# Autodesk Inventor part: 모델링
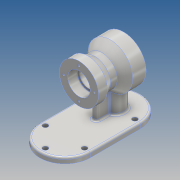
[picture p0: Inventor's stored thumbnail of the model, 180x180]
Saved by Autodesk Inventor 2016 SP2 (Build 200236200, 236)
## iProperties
Created: 2020-01
Part Number: 모델링
Material: 알루미늄 6061
Document SubType Name: Modeling
Designer: EZ
Density: 2.7 g/cm^3
Appearance: 알루미늄 - 평지
Author: EZ
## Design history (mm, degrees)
sketch "스케치1"
  geometry: L1 (-45, 0)-(-45, -90); L2 (45, 0)-(45, -90); L3 (0, 45)-(0, -135); A1 r 45 centre (0, 0) between (45, 0) and (-45, 0); A2 r 45 centre (0, -90) between (-45, -90) and (45, -90); 1 further point
  constraints: 6 end point, 6 point on circle, 2 centre point, 2 tangent, 1 coincident, 1 vertical
  dimensions: "d3" = 45 distance between parallel lines of L3 L1; "d4" = 180 distance of L3.end L3.start; "d6" = 90 distance between parallel lines of L2 L1
extrude "돌출1" new body sketch "스케치1" distance "d7" = 10; taper "d8" = 0 deg
fillet "모깎기1" dims "d9" = 3
sketch "스케치2"
  geometry: L1 (0, 0)-(-90, 0) reference; L2 (45, 0)-(45, 7) reference; L3 (15, 80)-(15, 120); L4 (15, 120)-(-9, 120); L5 (-9, 120)-(-23.897, 107.5); L6 (-23.897, 107.5)-(-36.01, 107.5); L7 (-36.01, 107.5)-(-49, 115); L8 (-49, 115)-(-65, 115); L9 (-65, 115)-(-65, 80); L10 (-65, 80)-(15, 80)
  constraints: 16 end point, 3 perpendicular, 2 parallel, 1 vertical
  dimensions: "d19" = 80 distance between parallel lines of L10 L1; "d20" = 80 distance between parallel lines of L9 L3; "d21" = 24 distance from line of L4.end L3; "d22" = 55 diameter of L6 L10; "d23" = 16 distance of L7.end L8.end; "d24" = 80 diameter of L4 L10; "d25" = 70 diameter of L8 L10; "d26" = 40 deg angle of L5 L6; "d27" = 30 deg angle of L7 L6; "d28" = 30 distance between parallel lines of L2 L3
revolve "회전1" sketch "스케치2" stored, may be unused: angle "d29" = 90 deg
sketch "스케치3"
  geometry: L1 (45, 0)-(45, -90) reference; L2 (-45, -90)-(-45, 0) reference; L3 (35, -90)-(35, 0); L4 (-35, 0)-(-35, -90); C1 r 4.5 at (35, 0); C2 r 4.5 at (35, -90); C3 r 4.5 at (0, -125); C4 r 4.5 at (-35, -90); C5 r 4.5 at (-35, 0); C6 r 4.5 at (0, 35); A1 r 45 centre (0, -90) between (-45, -90) and (45, -90) reference; A2 r 45 centre (0, 0) between (45, 0) and (-45, 0) reference; A3 r 35 centre (0, 0) between (35, 0) and (-35, 0); A4 r 35 centre (0, -90) between (-35, -90) and (35, -90); 4 further points
  constraints: 8 centre point, 8 point on circle, 5 coincident, 4 end point, 4 horizontal alignment, 2 point on line, 1 vertical alignment, 3 other
  dimensions: "d30" = 9 diameter of C1; "d31" = 9 diameter of C2; "d32" = 9 diameter of C3; "d33" = 9 diameter of C4; "d34" = 9 diameter of C5; "d35" = 9 diameter of C6; "d36" = 10 distance between parallel lines of L1 L3
extrude "돌출2" cut sketch "스케치3" distance "d37" = 10; taper "d38" = 0 deg
sketch "스케치4"
  geometry: L1 (45, -90)-(45, 0) reference; L2 (-45, 0)-(-45, -90) reference; L3 (0, 45)-(0, -135); L4 (5, -15.199)-(5, -34); L5 (-5, -15.199)-(-5, -34); A1 r 16 centre (0, 0) between (5, -15.199) and (-5, -15.199); A2 r 45 centre (0, 0) between (45, 0) and (-45, 0) reference; A3 r 45 centre (0, -90) between (-45, -90) and (45, -90) reference; A4 r 5 centre (0, -34) between (-5, -34) and (5, -34); 2 further points
  constraints: 7 point on circle, 6 end point, 2 centre point, 2 point on line, 2 tangent, 2 vertical, 1 coincident
  dimensions: "d39" = 32 diameter of A1; "d88" = 50 distance of point (0, 16) A4.centre; "d89" = 10 distance between parallel lines of L5 L4
extrude "돌출3" join sketch "스케치4" distance "d43" = 55; taper "d44" = 0 deg
sketch "스케치5"
  geometry: A1 r 40 centre (0, 0) between (-13.229, 37.749) and (13.229, 37.749) reference; 5 further points
  constraints: 1 vertical alignment, 5 other
  dimensions: "d45" = 33 distance of point (0, -33) A1.centre; "d48" = 360 deg dimension on A1.centre point (0, -33) (derived)
hole "구멍1" sketch "스케치5" at (0, -33), (33, 0), (0, 33), (-33, 0) diameter "d50" = 3.242; stored, may be unused: countersink angle "d54" = 90 deg, drill point angle "d56" = 118 deg; dims "d51" = 9, "d52" = 4, "d53" = 2, "d55" = 11
sketch "스케치6"
  geometry: C1 r 26 at (0, 0); A1 r 40 centre (0, 0) between (-13.229, 37.749) and (13.229, 37.749) reference; 1 further point
  constraints: 1 centre point, 1 coincident
  dimensions: "d57" = 52 diameter of C1
extrude "돌출4" cut sketch "스케치6" distance "d58" = 20; taper "d59" = 0 deg
fillet "모깎기2" dims "d60" = 0.3
chamfer "모따기1" distance "d61" = 1; stored, may be unused: second distance "d62" = 2, angle "d63" = 45 deg
sketch "스케치7"
  geometry: C1 r 35 at (0, 0) reference; 5 further points
  constraints: 1 vertical alignment, 5 other
  dimensions: "d64" = 27.5 distance of point (0, 27.5) C1.centre; "d67" = 360 deg dimension on C1.centre point (0, 27.5) (derived)
hole "구멍2" sketch "스케치7" at (0, 27.5), (-27.5, 0), (0, -27.5), (27.5, 0) diameter "d69" = 3.242; stored, may be unused: countersink angle "d73" = 90 deg, drill point angle "d75" = 118 deg; dims "d70" = 9, "d71" = 4, "d72" = 2, "d74" = 11
sketch "스케치8"
  geometry: C1 r 35 at (0, 0) reference; C2 r 20 at (0, 0); 1 further point
  constraints: 1 centre point, 1 coincident
  dimensions: "d76" = 40 diameter of C2
extrude "돌출5" cut sketch "스케치8" distance "d77" = 17; taper "d78" = 0 deg
sketch "스케치9"
  geometry: C1 r 35 at (0, 0) reference; C2 r 16 at (0, 0); A1 r 27.5 centre (0, 0) between (4.578, -27.116) and (-4.578, -27.116) reference; 1 further point
  constraints: 1 centre point, 1 coincident, 1 horizontal alignment
  dimensions: "d79" = 32 diameter of C2
extrude "돌출6" cut sketch "스케치9" stored distance "d80" = 17; taper "d81" = 0 deg
sketch "스케치10"
  geometry: L1 (6.573, 82.099)-(6.573, 45.203); L2 (6.573, 45.203)-(1.77, 45.203); L3 (1.77, 45.203)-(1.77, 82.099); L4 (1.77, 82.099)-(6.573, 82.099); L5 (0, 135)-(7, 135) reference; L6 (0, 90)-(0, 0) reference; 1 further point
  constraints: 2 other
  dimensions: "d82" = 70 distance from line of point (4, 65) L5; "d83" = 4 distance from line of point (4, 65) L6
feature "엠보싱1" sketch "스케치10" dims "d3" = 45, "d4" = 180, "d6" = 90, "d20" = 80, "d84" = 0.5, "d85" = 0
fillet "모깎기3" dims "d90" = 3
fillet "모깎기4" dims "d91" = 3
fillet "모깎기5" dims "d92" = 0.3
node "솔리드1"
node "투영된 루프1"
